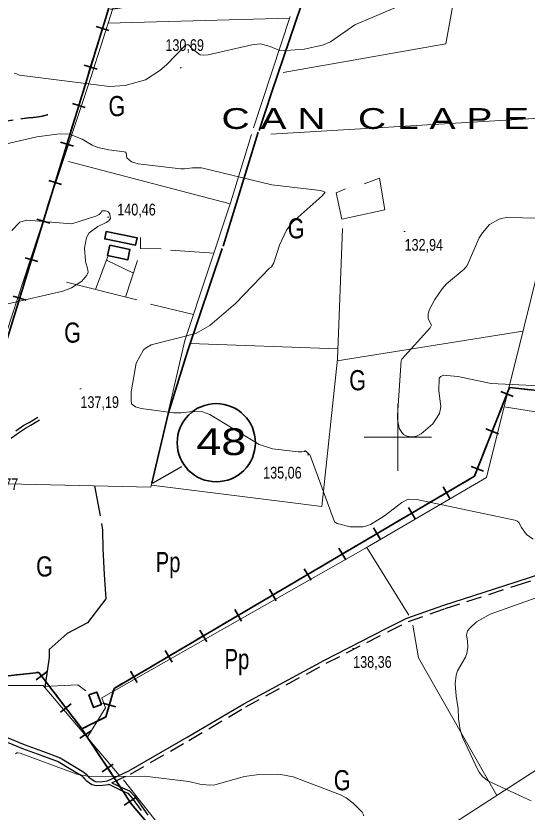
# Model space of a CAD drawing. Extents: x 483843 to 488449, y 4381269 to 4384483.
# Drawn here: x 486216 to 486596, y 4382221 to 4382814 of the extents above; entities that cross this region are included whole.
import ezdxf
from ezdxf.enums import TextEntityAlignment as Align

# ---------------------------------------------------------------- set-up
doc = ezdxf.new("R2010")
doc.units = 0
doc.header["$LTSCALE"] = 3.8
doc.linetypes.add('LONG_DASHED', pattern=[7.5, 6, -1.5])
doc.linetypes.add('MEDIUM_DASHED', pattern=[4.5, 3, -1.5])
for name, color, linetype, lineweight in [('1', 7, 'Continuous', 13), ('13', 7, 'Continuous', 35), ('25', 7, 'LONG_DASHED', 25), ('27', 7, 'Continuous', 25), ('34', 7, 'Continuous', 35), ('38', 7, 'Continuous', 25), ('47', 7, 'Continuous', 35), ('51', 7, 'Continuous', 13), ('6', 7, 'Continuous', 35), ('7', 7, 'Continuous', 13), ('9', 7, 'Continuous', 13)]:
    doc.layers.add(name, color=color, linetype=linetype, lineweight=lineweight)
doc.layers.add('31', color=7, linetype='Continuous')
doc.layers.add('5', color=7, linetype='Continuous')

msp = doc.modelspace()

# ---------------------------------------------------------------- linework, layer by layer
at = {"layer": '1'}
for p, q in [((486500, 4382525), (486500, 4382475)), ((486475, 4382500), (486525, 4382500))]:
    msp.add_line(p, q, dxfattribs=at)
at = {"layer": '25'}
msp.add_lwpolyline([(486274.53, 4382463.86), (486280.53, 4382430.89), (486280.74, 4382417.02), (486281.59, 4382397.98), (486282.79, 4382379.71), (486269.14, 4382361.95), (486254.16, 4382353.83), (486240.68, 4382342), (486240.65, 4382336.08), (486237.55, 4382313.89)], dxfattribs=at)
at = {"layer": '27'}
msp.add_spline([(486286.37, 4382818.73), (486339.99, 4382829.8), (486391.37, 4382851.5), (486440.09, 4382863.84), (486483.65, 4382864.6), (486530.94, 4382876.91), (486556.13, 4382891.91), (486581.09, 4382903.76), (486654.31, 4382924.49), (486662.47, 4382925.04), (486711.17, 4382931.08), (486727.4, 4382937.04), (486766.91, 4382937.87), (486808.31, 4382909.18), (486821.81, 4382880.51), (486820.67, 4382841.64), (486812.49, 4382812.89), (486799.42, 4382770.69), (486791.78, 4382745.03), (486785, 4382714.29), (486784.58, 4382691.25), (486792.33, 4382675.66), (486812.73, 4382668.89), (486834.8, 4382649.92), (486842.09, 4382627.43), (486847.24, 4382607.13), (486841.07, 4382582.93), (486840.3, 4382544.36), (486820.33, 4382480.87), (486817.63, 4382459.06), (486815.97, 4382420.47), (486812.52, 4382387.85), (486799.99, 4382362.84), (486771.04, 4382337.85), (486733.51, 4382314.2), (486712.72, 4382296.59), (486687.38, 4382263.88), (486690.96, 4382229.15), (486713.22, 4382200.82), (486764.33, 4382192.43), (486778.5, 4382149.68), (486779.01, 4382117.89), (486787.15, 4382072.98), (486813.93, 4382065.66), (486857.54, 4382071.08), (486866.35, 4382080.34), (486893.23, 4382096.95), (486915.85, 4382116.25), (486928.06, 4382127.9), (486936.43, 4382157.7), (486928.1, 4382176.05), (486914.22, 4382205.24), (486902.98, 4382218.81), (486885.61, 4382249.79), (486879.29, 4382279.36), (486884.99, 4382315.26), (486888.52, 4382343.76), (486907.35, 4382375.88), (486922.54, 4382388.35), (486945.58, 4382366.33), (486954.28, 4382323.31), (486963.51, 4382283.6), (486982.52, 4382253.24), (487009.26, 4382225.98), (487037.6, 4382230.32), (487058.96, 4382252.37), (487069.68, 4382284.84), (487065.95, 4382338.17), (487054.24, 4382363.72), (487038.01, 4382386.56), (487027.59, 4382400.37), (487012.06, 4382422.24), (486991.9, 4382450.1), (486977.88, 4382471.56), (486976.21, 4382486.9), (486980.43, 4382521.64), (487024.88, 4382562.69), (487055.81, 4382565.06), (487106.74, 4382596.8), (487155.96, 4382614.11), (487207.74, 4382666.72), (487232.21, 4382676.6), (487267.31, 4382683.94), (487282.71, 4382693.48), (487294.56, 4382707.98), (487340.16, 4382736.84), (487389.67, 4382736.07), (487421.36, 4382716.33), (487454.29, 4382680.57), (487455.44, 4382629.06), (487501.37, 4382598.97)], degree=3, dxfattribs=at)
at = {"layer": '34'}
for p, q in [((486285.16, 4382802.76), (486275.6, 4382805.7)), ((486281.85, 4382809.01), (486278.91, 4382799.45)), ((486277.45, 4382794.67), (486274.51, 4382785.11)), ((486276.37, 4382774.09), (486266.81, 4382777.02)), ((486273.05, 4382780.34), (486270.12, 4382770.78)), ((486268.65, 4382766), (486265.72, 4382756.44)), ((486264.26, 4382751.67), (486261.32, 4382742.11)), ((486267.57, 4382745.42), (486258.01, 4382748.35)), ((486259.86, 4382737.33), (486256.93, 4382727.77)), ((486255.46, 4382723), (486252.53, 4382713.44)), ((486258.78, 4382716.75), (486249.22, 4382719.68)), ((486251.06, 4382708.65), (486248.13, 4382699.09)), ((486246.67, 4382694.32), (486243.74, 4382684.76)), ((486249.98, 4382688.08), (486240.42, 4382691.01)), ((486242.27, 4382679.98), (486239.34, 4382670.42)), ((486241.19, 4382659.41), (486231.63, 4382662.34)), ((486237.87, 4382665.65), (486234.94, 4382656.09)), ((486233.47, 4382651.31), (486230.54, 4382641.75)), ((486232.39, 4382630.73), (486222.83, 4382633.67)), ((486229.08, 4382636.98), (486226.15, 4382627.42)), ((486224.68, 4382622.64), (486221.75, 4382613.08)), ((486223.6, 4382602.06), (486214.04, 4382605)), ((486220.28, 4382608.31), (486217.35, 4382598.75)), ((486585.8, 4382530.46), (486576.49, 4382534.13)), ((486582.98, 4382536.94), (486579.31, 4382527.64)), ((486597.84, 4382535.39), (486587.9, 4382536.47)), ((486577.48, 4382522.99), (486573.82, 4382513.68)), ((486571.99, 4382509.04), (486568.32, 4382499.74)), ((486574.81, 4382502.56), (486565.5, 4382506.22)), ((486566.49, 4382495.09), (486562.82, 4382485.78)), ((486563.81, 4382474.65), (486554.51, 4382478.32)), ((486560.99, 4382481.14), (486557.33, 4382471.83)), ((486553.47, 4382468.92), (486544.85, 4382463.84)), ((486540.55, 4382461.3), (486531.94, 4382456.22)), ((486538.79, 4382454.46), (486533.71, 4382463.07)), ((486527.63, 4382453.69), (486519.02, 4382448.61)), ((486514.72, 4382446.07), (486506.1, 4382440.99)), ((486512.95, 4382439.23), (486507.87, 4382447.84)), ((486501.8, 4382438.45), (486493.18, 4382433.38)), ((486487.12, 4382424), (486482.04, 4382432.61)), ((486488.88, 4382430.84), (486480.27, 4382425.76)), ((486475.96, 4382423.22), (486467.35, 4382418.15)), ((486463.05, 4382415.61), (486454.43, 4382410.53)), ((486461.28, 4382408.76), (486456.2, 4382417.38)), ((486450.13, 4382407.99), (486441.51, 4382402.91)), ((486435.45, 4382393.53), (486430.37, 4382402.15)), ((486437.21, 4382400.38), (486428.6, 4382395.3)), ((486424.29, 4382392.76), (486415.68, 4382387.68)), ((486411.38, 4382385.15), (486402.77, 4382380.07)), ((486409.61, 4382378.3), (486404.53, 4382386.92)), ((486383.78, 4382363.07), (486378.7, 4382371.69)), ((486398.46, 4382377.53), (486389.84, 4382372.45)), ((486385.55, 4382369.92), (486376.93, 4382364.84)), ((486372.62, 4382362.3), (486364.01, 4382357.22)), ((486359.71, 4382354.69), (486351.1, 4382349.61)), ((486357.94, 4382347.84), (486352.86, 4382356.46)), ((486346.79, 4382347.07), (486338.18, 4382341.99)), ((486333.88, 4382339.46), (486325.26, 4382334.38)), ((486332.11, 4382332.61), (486327.03, 4382341.23)), ((486320.96, 4382331.84), (486312.34, 4382326.76)), ((486216.38, 4382323.19), (486226.32, 4382324.27)), ((486238.96, 4382325.43), (486231.01, 4382319.36)), ((486308.04, 4382324.23), (486299.43, 4382319.15)), ((486306.27, 4382317.38), (486301.2, 4382325.99)), ((486241.05, 4382314.44), (486247.11, 4382306.49)), ((486257.14, 4382301.57), (486249.18, 4382295.51)), ((486250.13, 4382302.52), (486256.19, 4382294.56)), ((486290.27, 4382299.24), (486280.65, 4382301.98)), ((486286.83, 4382305.42), (486284.09, 4382295.8)), ((486259.22, 4382290.59), (486265, 4382283)), ((486282.07, 4382291.53), (486273.12, 4382287.06)), ((486268.66, 4382284.83), (486265, 4382283)), ((486265, 4382283), (486270.51, 4382274.66)), ((486271.92, 4382281.59), (486263.58, 4382276.08)), ((486273.26, 4382270.49), (486278.78, 4382262.15)), ((486288.45, 4382256.57), (486280.11, 4382251.06)), ((486281.53, 4382257.99), (486287.04, 4382249.64)), ((486289.8, 4382245.47), (486295.31, 4382237.13)), ((486304.99, 4382231.55), (486296.64, 4382226.04))]:
    msp.add_line(p, q, dxfattribs=at)
for points in [[(487676.62, 4383311.4), (487577, 4383232), (487304, 4383028), (487077, 4382869), (487054, 4382844), (487031, 4382851), (487023, 4382817), (486778, 4382653), (486740, 4382634), (486629, 4382532), (486583, 4382537), (486557, 4382471), (486289, 4382313), (486283, 4382292), (486265, 4382283)], [(486198, 4382961), (486252, 4382957), (486330, 4382966), (486207, 4382565)], [(486123, 4382313), (486233, 4382325), (486265, 4382283)], [(486231.29, 4382324.81), (486233, 4382325), (486238.02, 4382318.42)], [(486295.12, 4382316.61), (486289, 4382313), (486288.2, 4382310.22)], [(486265, 4382283), (486302, 4382227), (486409, 4382100), (486595, 4381820)], [(486298.06, 4382232.96), (486302, 4382227), (486303.84, 4382224.82)]]:
    msp.add_lwpolyline(points, dxfattribs=at)
at = {"layer": '38'}
for points in [[(486215.94, 4382504.72), (486221.96, 4382508.89), (486225.91, 4382511.07), (486232.43, 4382514.94)], [(486275.65, 4382243.51), (486280.38, 4382243.83), (486284.05, 4382244.28), (486300.02, 4382251.66), (486343.3, 4382276.72), (486385.61, 4382301.6), (486445.38, 4382334.13), (486491.46, 4382357.67), (486506.83, 4382365.34), (486534.3, 4382375.06), (486587.2, 4382392.22), (486638, 4382408.88), (486671.56, 4382425.18)], [(486116.41, 4382315.54), (486121.69, 4382313.98), (486129.6, 4382310.34), (486158.92, 4382297.46), (486222.1, 4382271.34), (486235.68, 4382266.41), (486248.88, 4382261.44), (486258.43, 4382255.57), (486266.6, 4382250.73), (486268.3, 4382249.18), (486269.39, 4382247.83), (486270.3, 4382246.94), (486274.09, 4382244.37), (486275.65, 4382243.51)], [(486157.67, 4382294.51), (486220.94, 4382268.36), (486234.57, 4382263.41), (486247.47, 4382258.55), (486256.78, 4382252.84), (486264.68, 4382248.15), (486265.96, 4382246.98), (486267.02, 4382245.67), (486268.27, 4382244.46), (486272.42, 4382241.64), (486275.83, 4382240.84)], [(486287.46, 4382242.9), (486295.29, 4382239.02), (486300.45, 4382236.88), (486304.14, 4382232.74), (486314.12, 4382218.7)]]:
    msp.add_lwpolyline(points, dxfattribs=at)
at = {"layer": '38', "linetype": 'MEDIUM_DASHED'}
for points in [[(486212.49, 4382499.36), (486217.31, 4382502.76), (486223.21, 4382506.86), (486227.09, 4382509), (486233.65, 4382512.88)], [(486287.46, 4382242.9), (486301.26, 4382249.28), (486344.65, 4382274.41), (486386.93, 4382299.27), (486446.63, 4382331.76), (486492.67, 4382355.28), (486507.88, 4382362.87), (486535.16, 4382372.52), (486588.03, 4382389.67), (486639.01, 4382406.39), (486672.73, 4382422.77)], [(486275.83, 4382240.84), (486280.63, 4382241.16), (486284.79, 4382241.67), (486285.06, 4382241.79)], [(486285.06, 4382241.79), (486294.43, 4382237.14), (486299.22, 4382235.15), (486302.53, 4382231.45), (486312.4, 4382217.55)]]:
    msp.add_lwpolyline(points, dxfattribs=at)
at = {"layer": '38', "linetype": 'LONG_DASHED'}
msp.add_spline([(486002.41, 4382273.58), (486006.82, 4382281.63), (486010.5, 4382294.08), (486011.32, 4382298.74), (486011.33, 4382306.55), (486011.49, 4382310.22), (486011.38, 4382320.43), (486011.34, 4382331.16), (486011.32, 4382340.91), (486013.77, 4382346.66), (486018.97, 4382358), (486022.33, 4382367.44), (486026.22, 4382380.87), (486030.95, 4382397.46), (486036.55, 4382411.74), (486040.05, 4382421.33), (486044.59, 4382432.14), (486048.67, 4382442.94), (486050.64, 4382445.9), (486062.61, 4382456.62), (486072.76, 4382463.93), (486076.16, 4382471.19), (486076.69, 4382483.58), (486076.55, 4382491.01), (486077.83, 4382516.39), (486080.04, 4382523.04), (486101.78, 4382565.89), (486105.9, 4382570.62), (486109.49, 4382575.78), (486121.64, 4382597.08), (486126.12, 4382606.62), (486132.11, 4382615.95), (486136.79, 4382626.61), (486137.01, 4382635.62), (486138.51, 4382644.2), (486139.76, 4382649.63), (486149.29, 4382679.28), (486159.19, 4382704.45), (486168.12, 4382713.08), (486188.13, 4382727.02), (486200.93, 4382732.95), (486207.2, 4382734.79), (486223.06, 4382737.62), (486235.56, 4382739.12), (486239.82, 4382740.25)], degree=3, dxfattribs=at)
at = {"layer": '47'}
for points in [[(486283.23, 4382653.11), (486282.13, 4382647.62), (486304.97, 4382643.06), (486306.07, 4382648.55)], [(486285.84, 4382643.11), (486300.83, 4382639.89), (486299.13, 4382631.99), (486284.14, 4382635.21)], [(486270.26, 4382308.19), (486273.73, 4382298.85), (486279.64, 4382301.04), (486276.17, 4382310.38)]]:
    msp.add_lwpolyline(points, close=True, dxfattribs=at)
at = {"layer": '51'}
for p, q in [((486284.66, 4382808.25), (486419.69, 4382812.02)), ((486392.78, 4382730.32), (486420.07, 4382813.17)), ((486632.47, 4382739.15), (486405.49, 4382725.62)), ((486255.15, 4382705.17), (486375.4, 4382673.72)), ((486363.23, 4382637.07), (486330.93, 4382639.25)), ((486284.55, 4382635.2), (486275.27, 4382609.99)), ((486283.34, 4382631.9), (486303.4, 4382622.27)), ((486297.51, 4382604.41), (486306.48, 4382631.61)), ((486253.57, 4382615.43), (486305.97, 4382602.28)), ((486316.09, 4382599.04), (486348.08, 4382591.47)), ((486454.97, 4382556.93), (486592.97, 4382579.07)), ((486455.39, 4382565.94), (486345.57, 4382569.84)), ((486476.99, 4382417.95), (486508.13, 4382367.69))]:
    msp.add_line(p, q, dxfattribs=at)
for points in [[(486269.04, 4382276.51), (486282.76, 4382298.7), (486279.91, 4382306.15), (486475.97, 4382417.35), (486565.92, 4382470.15), (486593.59, 4382581.58), (486631.16, 4382732.98), (486669.94, 4382915.82), (486561.72, 4382936.66), (486535.7, 4382792.93), (486414.87, 4382771.51)], [(486123.94, 4382322.16), (486158.44, 4382426.46), (486191.9, 4382526.39), (486225.82, 4382629.55), (486242.34, 4382679.25), (486271.84, 4382767.77), (486307.93, 4382881.7)], [(486177.49, 4382466.01), (486316.46, 4382462.92), (486341.63, 4382572.05), (486375.92, 4382675.29), (486391.23, 4382725.34)], [(486461.08, 4382684.95), (486454.09, 4382681.87), (486458.47, 4382662.47), (486490.43, 4382669.21), (486486.26, 4382692.75), (486474.95, 4382688.54)], [(486316.78, 4382464.29), (486415.99, 4382452.02), (486443.52, 4382448.47), (486455.1, 4382558.14), (486458.77, 4382655.35)], [(486324.08, 4382640.16), (486308.55, 4382640.51), (486308.68, 4382648.69)], [(486729.23, 4382613.34), (486650.57, 4382546.85), (486611.73, 4382517.54), (486578.97, 4382522.69)], [(486720.46, 4382428.98), (486758.35, 4382352.97), (486392.69, 4382116.17)], [(486511.21, 4382360.1), (486515.47, 4382335.74), (486573.59, 4382233.32)], [(486124.23, 4382315.34), (486236.36, 4382315.29), (486292.68, 4382248.44)], [(486237.1, 4382314.42), (486262.15, 4382315.75), (486268.1, 4382311.3)], [(486295.96, 4382244.9), (486365.15, 4382156.94), (486439.61, 4382046.67), (486483.97, 4381980.32), (486553.96, 4381879.48), (486560.46, 4381870.09)]]:
    msp.add_lwpolyline(points, dxfattribs=at)
at = {"layer": '6'}
msp.add_line((486396.11, 4382727.09), (486370.16, 4382642.32), dxfattribs=at)
at = {"layer": '6', "lineweight": 25}
msp.add_line((486317.67, 4382465.72), (486339.32, 4382478.32), dxfattribs=at)
at = {"layer": '6'}
for points in [[(486445.81, 4382873.41), (486406.24, 4382757.15), (486396.79, 4382728.38)], [(486369.4, 4382640.61), (486343.6, 4382563.91), (486329.34, 4382517.49), (486317.11, 4382465.75)]]:
    msp.add_lwpolyline(points, dxfattribs=at)
msp.add_circle((486365.01, 4382495.97), 29.1, dxfattribs=at)
at = {"layer": '7'}
for p, q in [((486338.09, 4382774.87), (486339.09, 4382774.87)), ((486284.01, 4382663.86), (486285.01, 4382663.86)), ((486504.52, 4382653.24), (486505.52, 4382653.24)), ((486263.5, 4382536.15), (486264.5, 4382536.15)), ((486432.83, 4382487.03), (486433.83, 4382487.03)), ((486466.3, 4382342.75), (486467.3, 4382342.75))]:
    msp.add_line(p, q, dxfattribs=at)
at = {"layer": '9'}
for points in [[(486497.71, 4382819.69), (486468.09, 4382806.96), (486449.92, 4382794.22), (486443.98, 4382791.96), (486430.28, 4382788.94), (486416.91, 4382787.82), (486411.44, 4382788.23), (486405.04, 4382790.85), (486397.89, 4382792.76), (486391.36, 4382792.17), (486358.87, 4382784.63), (486355.63, 4382784.51), (486352.92, 4382784.77), (486347.44, 4382788.77), (486344.41, 4382792.2), (486343.23, 4382792.1), (486341.91, 4382791.53), (486328.08, 4382777.26), (486322.96, 4382773.03), (486312.3, 4382766.12), (486297.14, 4382761.72), (486285.64, 4382761.04), (486218.65, 4382769.55), (486216.38, 4382770.47), (486214.74, 4382770.76)], [(486454.81, 4382435.94), (486453.01, 4382437.16), (486434.49, 4382487.21), (486433.88, 4382487.46), (486433.68, 4382487.62), (486431.55, 4382489.76), (486431.34, 4382489.86), (486431.16, 4382489.9), (486430.71, 4382489.53), (486428.61, 4382489.07), (486425.9, 4382489.09), (486406.82, 4382491.44), (486396.89, 4382494.73), (486360.16, 4382516.93), (486354.83, 4382518.92), (486347.03, 4382519.27), (486338.93, 4382518.24), (486333.18, 4382518.27), (486309.06, 4382521.37), (486305.03, 4382522.56), (486301.9, 4382524.89), (486301.6, 4382527.75), (486301.71, 4382533.82), (486305.39, 4382555.08), (486310.97, 4382565.08), (486313.58, 4382567.1), (486316.64, 4382568.8), (486349.76, 4382577.23), (486360.12, 4382583.17), (486379.29, 4382599.62), (486404.55, 4382625.93), (486405.99, 4382626.82), (486407.73, 4382629.73), (486412.14, 4382642.9), (486417.2, 4382654.2), (486421.35, 4382659.96), (486443.69, 4382679.75), (486445.92, 4382682.46), (486442.53, 4382683.67), (486406.26, 4382687.85), (486354, 4382700.66), (486347.45, 4382700.57), (486341.35, 4382699.71), (486338.68, 4382699.72), (486306.88, 4382703.47), (486302.01, 4382704.93), (486298.47, 4382707.92), (486298.1, 4382711.44), (486297.75, 4382712.12), (486297.33, 4382712.22), (486296.61, 4382712.48), (486285.2, 4382713.84), (486277.01, 4382715.6), (486272.7, 4382717.35), (486265.32, 4382721.91), (486255.82, 4382725.51), (486248.51, 4382725.9), (486231.61, 4382723.71), (486204.9, 4382717.39)], [(486209.89, 4382599.28), (486250.87, 4382608.78), (486257.4, 4382611.28), (486265.03, 4382616.11), (486268.71, 4382620.68), (486269.27, 4382621.78), (486269.64, 4382622.81), (486269.34, 4382625.94), (486268.04, 4382629.84), (486267.77, 4382631.36), (486267.09, 4382640.77), (486268.47, 4382648.66), (486269.41, 4382650.48), (486270.58, 4382652.13), (486276.83, 4382656.77), (486283.04, 4382659.88), (486285.11, 4382661.18), (486286.34, 4382662.79), (486286.04, 4382663.98), (486285.78, 4382666.1), (486285.24, 4382667.38), (486284.93, 4382667.66), (486284.55, 4382667.91), (486282.57, 4382668.54), (486280.61, 4382668.63), (486280.24, 4382668.53), (486279.94, 4382668.37), (486279.49, 4382667.38), (486277.84, 4382665.77), (486275.48, 4382664.65), (486257.69, 4382658.77), (486224.24, 4382661.63), (486221.39, 4382660.97), (486218.91, 4382660.01), (486213.03, 4382654.01)], [(486605.49, 4382538.2), (486569.4, 4382540.14), (486544.65, 4382545.3), (486533.73, 4382546.27), (486531.94, 4382545.36), (486530.68, 4382543.93), (486530.57, 4382534.54), (486531.94, 4382523.03), (486531.6, 4382520.28), (486530.96, 4382517.71), (486526.08, 4382509.99), (486517.38, 4382502.61), (486513.91, 4382500.73), (486511.23, 4382500.27), (486509.72, 4382500.28), (486506.92, 4382500.77), (486504.29, 4382502.18), (486503.63, 4382502.8), (486503.01, 4382503.51), (486501.01, 4382506.89), (486499.87, 4382513.5), (486499.78, 4382516.24), (486502.52, 4382557.05), (486503.02, 4382558.13), (486524.05, 4382581.38), (486525.04, 4382583.52), (486522.67, 4382588.09), (486522.47, 4382591.95), (486523.52, 4382595.11), (486527.49, 4382602.67), (486532.97, 4382610.56), (486536.14, 4382614.17), (486549.32, 4382625.08), (486551.46, 4382627.74), (486560.41, 4382648.48), (486562.86, 4382652.25), (486568.12, 4382658.31), (486575.44, 4382662.45), (486578, 4382663.09), (486580.79, 4382663.51), (486604.64, 4382663.15)], [(486600.68, 4382424.04), (486595.57, 4382427.68), (486592.01, 4382432.88), (486590.01, 4382436.64), (486588.72, 4382437.49), (486587.1, 4382438.27), (486514.16, 4382453.79), (486507.63, 4382453.94), (486503.1, 4382451.42), (486490.07, 4382441.61), (486479.64, 4382435.08), (486476.87, 4382434.01), (486474.14, 4382433.26), (486464.69, 4382433.23), (486454.81, 4382435.94)], [(486599.23, 4382229.28), (486567.47, 4382244), (486563.28, 4382247.26), (486560.56, 4382250.79), (486559.51, 4382252.57), (486548.07, 4382276.89), (486546.37, 4382282.33), (486545.18, 4382290.32), (486544.92, 4382297.9), (486543.37, 4382307.28), (486542.73, 4382316.38), (486543.31, 4382322.94), (486544.31, 4382326.23), (486550.37, 4382336.39), (486551.4, 4382339.07), (486552.07, 4382343.87), (486551.86, 4382348.17), (486551.14, 4382352.94), (486551.88, 4382355.84), (486553.47, 4382357.94), (486558.46, 4382362.65), (486568.63, 4382368.39), (486628.69, 4382389.61)], [(486474.54, 4382218.28), (486474.43, 4382218.92), (486473.51, 4382220.86), (486466.86, 4382227.73), (486461.52, 4382231.63), (486457.33, 4382233.93), (486422.11, 4382247.2), (486412.98, 4382248.91), (486410.27, 4382249.14), (486396.72, 4382248.93), (486386.04, 4382247.5), (486363.96, 4382241.37), (486359.84, 4382241), (486352.85, 4382241.85), (486344.7, 4382243.7), (486311.65, 4382247.85), (486270.66, 4382247.51), (486261.31, 4382249.14), (486219.18, 4382264.84), (486217.36, 4382265.14), (486216.96, 4382265.11), (486216.61, 4382265.03), (486215.72, 4382264.34)]]:
    msp.add_lwpolyline(points, dxfattribs=at)

# ---------------------------------------------------------------- texts
at = {"layer": '13', "width": 1.25}
msp.add_text('48', height=20, dxfattribs=at).set_placement((486350.15, 4382486.73))
at = {"layer": '31'}
for s, width, p in [('G', 0.8, (486291.07, 4382739.01)), ('G', 0.8, (486424.38, 4382648)), ('G', 0.8, (486258.14, 4382570.42)), ('G', 0.8, (486470.08, 4382534.99)), ('Pp', 0.75, (486329.17, 4382399.62)), ('G', 0.8, (486237.25, 4382396.35)), ('Pp', 0.75, (486380.4, 4382327.42)), ('G', 0.8, (486458.61, 4382237.24))]:
    msp.add_text(s, height=15, dxfattribs=dict(at, width=width)).set_placement(p, align=Align.CENTER)
at = {"layer": '5', "width": 1.4}
msp.add_text('C A N   C L A P E S', height=15.49, dxfattribs=at).set_placement((486368.88, 4382729.51))
at = {"layer": '7', "width": 0.8}
for s, p in [('130,69', (486327.19, 4382787.53)), ('140,46', (486291.39, 4382665.13)), ('132,94', (486505.02, 4382638.87)), ('137,19', (486264, 4382521.78)), ('135,06', (486399.87, 4382469.28)), ('134,77', (486189.06, 4382460.71)), ('138,36', (486466.8, 4382328.38))]:
    msp.add_text(s, height=8.75, dxfattribs=at).set_placement(p)

doc.saveas('drawing.dxf')
